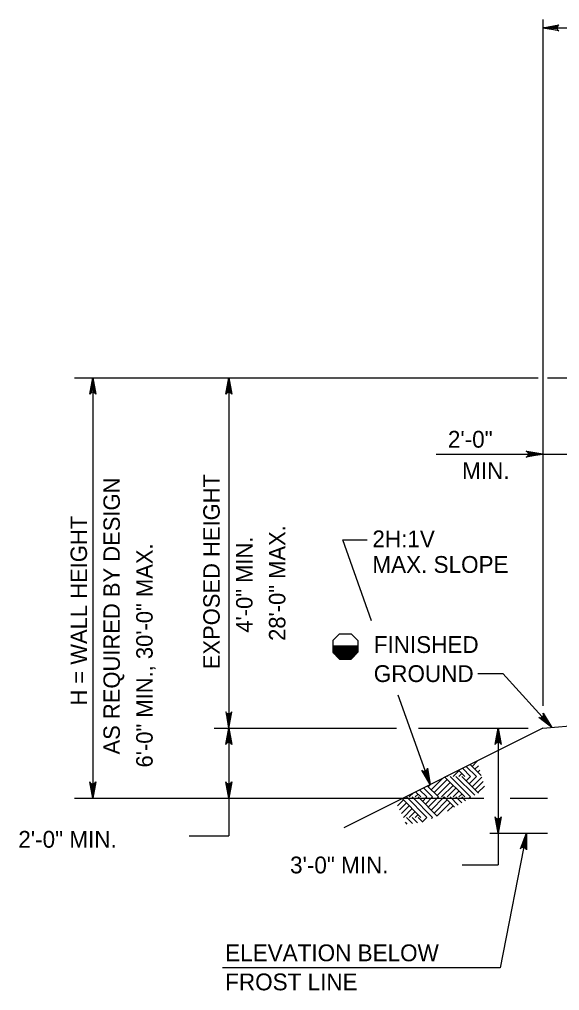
# Model space of a CAD drawing. Extents: x 3385 to 6532, y -616 to 1166.
# Drawn here: x 4025.9 to 4124.6, y 185.5 to 363 of the extents above; entities that cross this region are included whole.
import ezdxf

# ---------------------------------------------------------------- set-up
doc = ezdxf.new("R2010")
doc.units = 0
doc.layers.add('1', color=7, linetype='Continuous')

msp = doc.modelspace()

# ---------------------------------------------------------------- linework, layer by layer
at = {"layer": '1'}
for p, q in [((4121.51, 362.95), (4121.51, 237.52)), ((4121.51, 361.41), (4198.31, 361.41)), ((4035.98, 297.43), (4120.71, 297.43)), ((4039.29, 297.43), (4039.29, 220.62)), ((4064.15, 297.43), (4064.15, 213.73)), ((4122.4, 297.43), (4129.58, 297.43)), ((4102.04, 283.52), (4138.19, 283.52)), ((4090.26, 253.06), (4085, 267.82)), ((4085, 267.82), (4089.41, 267.82)), ((4084.39, 250.67), (4083.14, 249.42)), ((4084.39, 250.67), (4086.51, 250.67)), ((4086.51, 250.67), (4087.76, 249.42)), ((4083.13, 248.48), (4087.75, 248.48)), ((4083.14, 249.42), (4083.14, 247.3)), ((4086.23, 248.48), (4087.75, 248.48)), ((4087.76, 249.42), (4087.76, 247.3)), ((4083.13, 247.58), (4087.75, 247.58)), ((4083.13, 247.48), (4087.75, 247.48)), ((4083.13, 247.38), (4087.75, 247.38)), ((4083.14, 248.08), (4087.75, 248.08)), ((4083.14, 247.98), (4087.75, 247.98)), ((4083.14, 247.88), (4087.75, 247.88)), ((4083.14, 247.78), (4087.75, 247.78)), ((4083.14, 247.68), (4087.75, 247.68)), ((4084.39, 246.05), (4083.14, 247.3)), ((4083.15, 248.38), (4087.75, 248.38)), ((4083.15, 248.28), (4087.75, 248.28)), ((4083.15, 248.18), (4087.75, 248.18)), ((4083.15, 247.28), (4087.7, 247.28)), ((4083.25, 247.18), (4087.61, 247.18)), ((4083.35, 247.08), (4087.51, 247.08)), ((4083.45, 246.98), (4087.41, 246.98)), ((4083.56, 246.88), (4087.32, 246.88)), ((4083.66, 246.78), (4087.22, 246.78)), ((4086.51, 246.05), (4087.76, 247.3)), ((4083.76, 246.68), (4087.13, 246.68)), ((4083.86, 246.58), (4087.03, 246.58)), ((4083.96, 246.48), (4086.93, 246.48)), ((4084.07, 246.38), (4086.84, 246.38)), ((4084.17, 246.28), (4086.74, 246.28)), ((4084.27, 246.18), (4086.65, 246.18)), ((4084.37, 246.08), (4086.55, 246.08)), ((4084.39, 246.05), (4086.51, 246.05)), ((4109.66, 243.41), (4114.2, 243.41)), ((4114.2, 243.41), (4123.2, 233.57)), ((4100.93, 223.13), (4095.1, 239.47)), ((4061.49, 233.42), (4094.81, 233.42)), ((4121.51, 233.42), (4085.15, 215.24)), ((4098.82, 233.42), (4118.87, 233.42)), ((4113.38, 233.42), (4113.38, 208.47)), ((4121.51, 233.42), (4131.64, 234.27)), ((4108.6, 226.45), (4109.53, 227.38)), ((4105.13, 224.58), (4106.2, 225.65)), ((4107.27, 224.58), (4106.12, 225.73)), ((4108.33, 224.58), (4106.83, 226.09)), ((4109.4, 224.58), (4107.54, 226.44)), ((4110.3, 224.75), (4108.25, 226.8)), ((4109.13, 225.92), (4109.77, 226.56)), ((4109.67, 225.38), (4110.01, 225.73)), ((4101.13, 222.18), (4103.24, 224.29)), ((4101.67, 221.65), (4104.07, 224.05)), ((4107.27, 220.85), (4103.63, 224.49)), ((4104.07, 224.58), (4104.31, 224.83)), ((4108.33, 220.85), (4104.6, 224.58)), ((4109.09, 221.16), (4105.67, 224.58)), ((4106.2, 224.58), (4106.73, 225.12)), ((4109.76, 221.56), (4106.73, 224.58)), ((4107.53, 223.78), (4108.33, 224.58)), ((4108.07, 223.25), (4109.4, 224.58)), ((4108.6, 222.72), (4110.37, 224.49)), ((4109.13, 222.18), (4110.61, 223.66)), ((4110.2, 224.85), (4110.25, 224.9)), ((4100.33, 220.85), (4099.01, 222.17)), ((4101.4, 220.85), (4099.72, 222.53)), ((4102.47, 220.85), (4100.43, 222.89)), ((4100.6, 222.72), (4101.11, 223.23)), ((4102.2, 221.12), (4104.6, 223.52)), ((4103, 220.85), (4105.13, 222.98)), ((4104.07, 220.85), (4105.67, 222.45)), ((4105.13, 220.85), (4106.2, 221.92)), ((4109.67, 221.65), (4110.85, 222.84)), ((4035.98, 220.62), (4110.75, 220.62)), ((4095.01, 219.26), (4096.07, 220.32)), ((4099.27, 217.12), (4095.81, 220.57)), ((4100.33, 217.12), (4096.6, 220.85)), ((4097.13, 220.85), (4097.91, 221.63)), ((4101.4, 217.12), (4097.67, 220.85)), ((4098.2, 220.85), (4098.73, 221.38)), ((4099.27, 220.85), (4098.3, 221.82)), ((4102.21, 217.37), (4098.73, 220.85)), ((4099.53, 220.05), (4100.33, 220.85)), ((4100.07, 219.52), (4101.4, 220.85)), ((4100.6, 218.98), (4102.47, 220.85)), ((4101.13, 218.45), (4103.53, 220.85)), ((4101.67, 217.92), (4104.07, 220.32)), ((4105.41, 218.97), (4103.53, 220.85)), ((4106.08, 219.37), (4104.6, 220.85)), ((4106.75, 219.77), (4105.67, 220.85)), ((4106.2, 220.85), (4106.73, 221.38)), ((4107.42, 220.16), (4106.73, 220.85)), ((4107.98, 220.5), (4108.33, 220.85)), ((4115.55, 220.62), (4122.4, 220.62)), ((4094.67, 219.99), (4094.71, 220.03)), ((4095.35, 218.53), (4096.6, 219.78)), ((4095.69, 217.81), (4097.13, 219.25)), ((4096.07, 217.12), (4097.67, 218.72)), ((4102.2, 217.38), (4104.6, 219.78)), ((4104.13, 218.24), (4105.13, 219.25)), ((4097.71, 216), (4096.6, 217.12)), ((4097.13, 217.12), (4098.2, 218.18)), ((4098.66, 216.13), (4097.67, 217.12)), ((4098.2, 217.12), (4098.73, 217.65)), ((4099.6, 216.25), (4098.73, 217.12)), ((4099.53, 216.32), (4100.33, 217.12)), ((4101.19, 216.91), (4101.4, 217.12)), ((4096.77, 215.88), (4096.43, 216.22)), ((4096.54, 215.99), (4096.6, 216.05)), ((4056.94, 213.73), (4064.15, 213.73)), ((4111.84, 214.22), (4122.4, 214.22)), ((4106.82, 208.47), (4113.38, 208.47))]:
    msp.add_line(p, q, dxfattribs=at)
for points in [[(4121.51, 361.41), (4124.49, 361.97), (4124.26, 361.81), (4124.14, 361.61), (4124.11, 361.41), (4124.14, 361.21), (4124.26, 361.01), (4124.49, 360.85), (4121.51, 361.41), (4124.26, 361.01), (4124.14, 361.21), (4121.51, 361.41), (4124.11, 361.41), (4124.14, 361.61), (4121.51, 361.41), (4124.26, 361.81)], [(4039.29, 297.43), (4039.85, 294.44), (4039.69, 294.67), (4039.49, 294.79), (4039.29, 294.83), (4039.09, 294.79), (4038.89, 294.67), (4038.73, 294.44), (4039.29, 297.43), (4038.89, 294.67), (4039.09, 294.79), (4039.29, 297.43), (4039.29, 294.83), (4039.49, 294.79), (4039.29, 297.43), (4039.69, 294.67)], [(4064.15, 297.43), (4064.71, 294.44), (4064.55, 294.67), (4064.35, 294.79), (4064.15, 294.83), (4063.95, 294.79), (4063.75, 294.67), (4063.59, 294.44), (4064.15, 297.43), (4063.75, 294.67), (4063.95, 294.79), (4064.15, 297.43), (4064.15, 294.83), (4064.35, 294.79), (4064.15, 297.43), (4064.55, 294.67)], [(4121.51, 283.52), (4118.52, 282.97), (4118.64, 283.04), (4118.75, 283.12), (4118.81, 283.22), (4118.87, 283.32), (4118.89, 283.42), (4118.91, 283.52), (4118.89, 283.62), (4118.87, 283.72), (4118.81, 283.82), (4118.75, 283.92), (4118.64, 284), (4118.52, 284.08), (4121.51, 283.52), (4118.64, 284), (4118.75, 283.92), (4121.51, 283.52), (4118.81, 283.82), (4118.87, 283.72), (4121.51, 283.52), (4118.89, 283.62), (4118.91, 283.52), (4121.51, 283.52), (4118.89, 283.42), (4118.87, 283.32), (4121.51, 283.52), (4118.81, 283.22), (4118.75, 283.12), (4121.51, 283.52), (4118.64, 283.04)], [(4064.15, 233.42), (4064.71, 236.41), (4064.55, 236.18), (4064.35, 236.06), (4064.15, 236.02), (4063.95, 236.06), (4063.75, 236.18), (4063.59, 236.41), (4064.15, 233.42), (4063.75, 236.18), (4063.95, 236.06), (4064.15, 233.42), (4064.15, 236.02), (4064.35, 236.06), (4064.15, 233.42), (4064.55, 236.18)], [(4123.2, 233.57), (4120.78, 235.39), (4121.05, 235.33), (4121.28, 235.38), (4121.45, 235.49), (4121.57, 235.65), (4121.64, 235.87), (4121.6, 236.14), (4123.2, 233.57), (4121.64, 235.87), (4121.57, 235.65), (4123.2, 233.57), (4121.45, 235.49), (4121.28, 235.38), (4123.2, 233.57), (4121.05, 235.33)], [(4064.15, 233.42), (4064.71, 230.44), (4064.55, 230.67), (4064.35, 230.79), (4064.15, 230.82), (4063.95, 230.79), (4063.75, 230.67), (4063.59, 230.44), (4064.15, 233.42), (4063.75, 230.67), (4063.95, 230.79), (4064.15, 233.42), (4064.15, 230.82), (4064.35, 230.79), (4064.15, 233.42), (4064.55, 230.67)], [(4113.38, 233.42), (4113.94, 230.44), (4113.78, 230.67), (4113.58, 230.79), (4113.38, 230.82), (4113.18, 230.79), (4112.98, 230.67), (4112.82, 230.44), (4113.38, 233.42), (4112.98, 230.67), (4113.18, 230.79), (4113.38, 233.42), (4113.38, 230.82), (4113.58, 230.79), (4113.38, 233.42), (4113.78, 230.67)], [(4100.93, 223.13), (4099.4, 225.76), (4099.63, 225.59), (4099.85, 225.55), (4100.05, 225.58), (4100.23, 225.68), (4100.38, 225.86), (4100.45, 226.13), (4100.93, 223.13), (4100.38, 225.86), (4100.23, 225.68), (4100.93, 223.13), (4100.05, 225.58), (4099.85, 225.55), (4100.93, 223.13), (4099.63, 225.59)], [(4039.29, 220.62), (4038.73, 223.61), (4038.89, 223.38), (4039.09, 223.26), (4039.29, 223.22), (4039.49, 223.26), (4039.69, 223.38), (4039.85, 223.61), (4039.29, 220.62), (4039.69, 223.38), (4039.49, 223.26), (4039.29, 220.62), (4039.29, 223.22), (4039.09, 223.26), (4039.29, 220.62), (4038.89, 223.38)], [(4064.15, 220.62), (4063.59, 223.61), (4063.75, 223.38), (4063.95, 223.26), (4064.15, 223.22), (4064.35, 223.26), (4064.55, 223.38), (4064.71, 223.61), (4064.15, 220.62), (4064.55, 223.38), (4064.35, 223.26), (4064.15, 220.62), (4064.15, 223.22), (4063.95, 223.26), (4064.15, 220.62), (4063.75, 223.38)], [(4113.38, 214.22), (4112.82, 217.21), (4112.98, 216.98), (4113.18, 216.86), (4113.38, 216.82), (4113.58, 216.86), (4113.78, 216.98), (4113.94, 217.21), (4113.38, 214.22), (4113.78, 216.98), (4113.58, 216.86), (4113.38, 214.22), (4113.38, 216.82), (4113.18, 216.86), (4113.38, 214.22), (4112.98, 216.98)], [(4118.56, 214.22), (4113.77, 189.61), (4063.03, 189.61)], [(4118.56, 214.22), (4118.54, 211.19), (4118.49, 211.32), (4118.43, 211.45), (4118.34, 211.52), (4118.26, 211.6), (4118.16, 211.64), (4118.07, 211.67), (4117.96, 211.67), (4117.86, 211.68), (4117.75, 211.64), (4117.64, 211.6), (4117.54, 211.5), (4117.44, 211.4), (4118.56, 214.22), (4117.54, 211.5), (4117.64, 211.6), (4118.56, 214.22), (4117.75, 211.64), (4117.86, 211.68), (4118.56, 214.22), (4117.96, 211.67), (4118.07, 211.67), (4118.56, 214.22), (4118.16, 211.64), (4118.26, 211.6), (4118.56, 214.22), (4118.34, 211.52), (4118.43, 211.45), (4118.56, 214.22), (4118.49, 211.32)]]:
    msp.add_lwpolyline(points, dxfattribs=at)

# ---------------------------------------------------------------- texts
for s, height, p in [('2\'-0"', 3.072, (4104.19, 284.69)), ('MIN.', 3.072, (4106.79, 278.95)), ('2H:1V', 3.072, (4090.39, 266.48)), ('MAX. SLOPE', 3.072, (4090.39, 261.81)), ('FINISHED', 3.072, (4090.64, 247.17)), ('GROUND', 3.072, (4090.64, 241.86)), ('2\'-0" MIN.', 3.072, (4025.69, 211.58)), ('3\'-0" MIN.', 3.072, (4075.35, 206.89)), ('ELEVATION BELOW', 3.0721, (4063.49, 190.83)), ('FROST LINE', 3.072, (4063.49, 185.52))]:
    msp.add_text(s, height=height, dxfattribs=at).set_placement(p)
for s, p in [('AS REQUIRED BY DESIGN', (4044.24, 228.62)), ('EXPOSED HEIGHT', (4062.49, 244.2)), ('H = WALL HEIGHT', (4038.24, 237.56)), ('28\'-0" MAX.', (4074.49, 249.38)), ('4\'-0" MIN.', (4068.49, 250.88)), ('6\'-0" MIN., 30\'-0" MAX.', (4050.24, 226.25))]:
    msp.add_text(s, height=3, rotation=90, dxfattribs=at).set_placement(p)

doc.saveas('drawing.dxf')
